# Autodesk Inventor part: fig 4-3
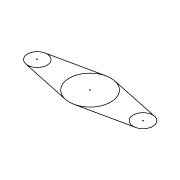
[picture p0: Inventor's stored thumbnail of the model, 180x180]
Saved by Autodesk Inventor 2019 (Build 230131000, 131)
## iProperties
Created: 2005-02
Part Number: fig 4-3
Document SubType Name: Modeling
Designer: CADCIM
Manufacturer: Standard
Standards Organization: Custom
Density: 1 g/cm^3
Material: Generic
Appearance: Default
Author: CADCIM
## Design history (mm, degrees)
sketch "Sketch1"
  geometry: L1 (-33.874, 5.844)-(-2.722, 12.469); L2 (2.595, 12.472)-(33.871, 5.852); L3 (-33.884, -5.902)-(-2.745, -12.585); L4 (2.595, -12.592)-(33.871, -5.972); A1 r 12.81 centre (-0.057, -0.06) between (-2.722, 12.469) and (2.595, 12.472); A2 r 6.006 centre (-32.624, -0.03) between (-33.874, 5.844) and (-33.884, -5.902); A3 r 6.043 centre (32.619, -0.06) between (33.871, 5.852) and (33.871, -5.972)
  constraints: 8 end point, 8 point on circle, 8 tangent, 3 centre point, 1 other
